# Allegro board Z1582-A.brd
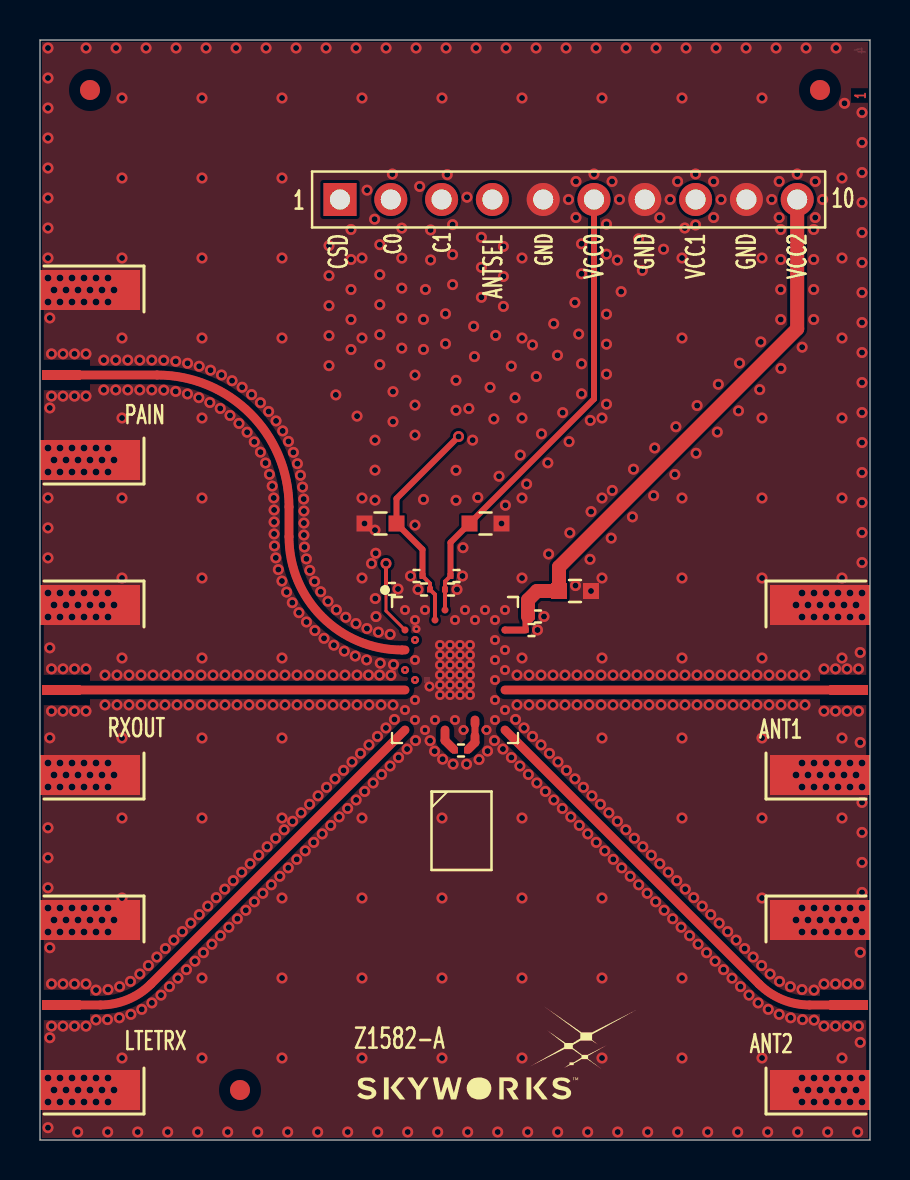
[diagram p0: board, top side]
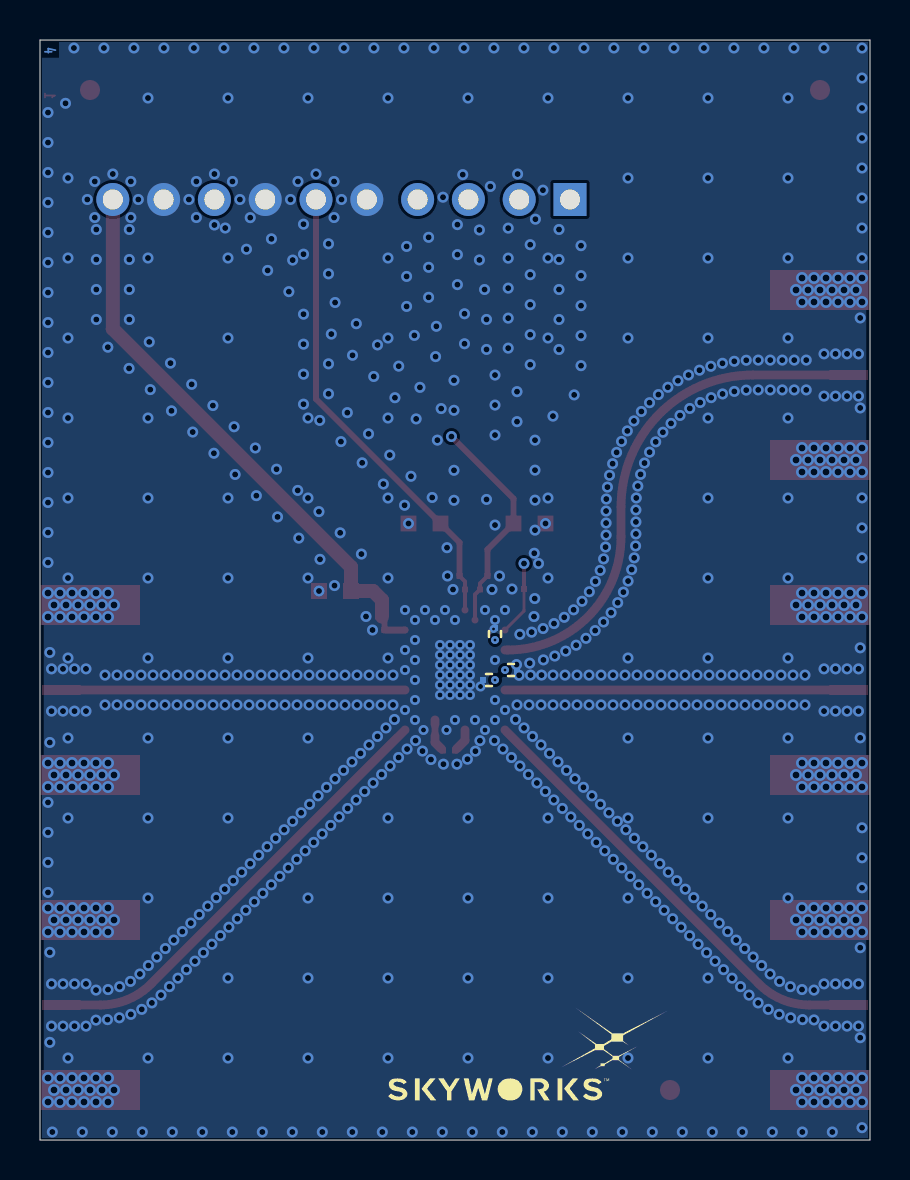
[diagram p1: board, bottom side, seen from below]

Outline 41.5 x 55 mm; copper layers: TOP, L2, L3, BOTTOM. Coordinates in mm from the lower left corner of the outline.
Outline path: 0,55 0,0 41.5,0 41.5,55 0,55

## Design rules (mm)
constraint set DEFAULT: min track width 0.15
net group RF: nets ANT1 ANT2 LTETRX N13114708 N13124264 PAIN RXOUT
nets with their own width: min track width 0.5; nets GND

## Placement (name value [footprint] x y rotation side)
C2  20pF  [SMDC600X300]  24.57 25.5 0 top
C3  20pF  [SMDC600X300]  19.2 27.52 180 top
C4  100pF  [SMDC600X300]  24.9 26.18 0 top
C5  20pF  [SMDC600X300]  20.55 27.52 0 top
C6  100pF  [SMDC600X300]  20.82 28.2 0 top
C7  100pF  [SMDC600X300]  18.82 28.2 180 top
C8  DNI  [SMDC600X300]  17.6 27.55 0 top
C9  DNI  [SMDC600X300]  18.75 25.3 90 bottom
C10  DNI  [SMDC600X300]  17.95 23.5 180 bottom
C11  DNI  [SMDC600X300]  19.05 23 0 bottom
C12  1uF  [SMDC1600X800]  26.75 27.45 0 top
C13  1uF  [SMDC1600X800]  22.27 30.82 0 top
C14  1uF  [SMDC1600X800]  17.02 30.82 180 top
J1  RF_5pin  [SMA_CPWG_442_236]  0 6.75 180 top
J2  RF_5pin  [SMA_CPWG_442_236]  0 38.25 180 top
J3  RF_5pin  [SMA_CPWG_442_236]  41.5 6.75 0 top
J4  RF_5pin  [SMA_CPWG_442_236]  0 22.5 180 top
J5  RF_5pin  [SMA_CPWG_442_236]  41.5 22.5 0 top
J6  HEADER 10  [TSW-110-07-G-S]  15 47.02 0 top
NOREF  -  []  0 0 90 top
NOREF#2  -  [unnamed#2]  39 52.5 0 top
NOREF#3  -  []  0 55 0 top
NOREF#4  -  []  -103.71 -52.7 0 top
NOREF#5  -  [unnamed#2]  10 2.5 0 top
NOREF#6  -  [unnamed#2]  2.5 52.5 0 top
NOREF#7  -  []  -78.31 -116.2 0 top
NOREF#8  -  []  15.43 1.55 0 top
NOREF#9  -  []  86.8 64.75 0 top
NOREF#10  -  []  24.52 1.5 180 bottom
R1  0R  [SMDC600X300]  21.05 19.48 0 top
U1  SKY66425-11  [SP03-D512_01]  20.75 23.5 0 top

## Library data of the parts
C2-C14 = C
J1-J5 = RF_5pin
J6 = HEADER 10
R1 = R
U1 = SKY66425-11

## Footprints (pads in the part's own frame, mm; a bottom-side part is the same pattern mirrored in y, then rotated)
SMA_CPWG_442_236
  rect 1.932x0.5 smd: 1(-1.1,0)
  rect 5x2 smd: 2(-2.5,4.25) 3(-2.5,-4.25) 4(-2.5,4.25) 5(-2.5,-4.25)
SMDC600X300
  rect 0.3x0.3 smd: 1(-0.3,0) 2(0.3,0)
SMDC1600X800
  rect 0.8x0.8 smd: 1(-0.8,0) 2(0.8,0)
SP03-D512_01
  round 0.35 smd: A01(-2.5,3) A03(-2.5,2) A05(-2.5,1) A07(-2.5,0) A09(-2.5,-1) A11(-2.5,-2) A13(-2.5,-3) B02(-2,2.5) B04(-2,1.5) B06(-2,0.5) B08(-2,-0.5) B10(-2,-1.5) B12(-2,-2.5) C01(-1.5,3) C13(-1.5,-3) D02(-1,2.5) D04(-0.75,1.25) D05(-0.75,0.75) D06(-0.75,0.25) D07(-0.75,-0.25) D08(-0.75,-0.75) D09(-0.75,-1.25) D12(-1,-2.5) E01(-0.5,3) E04(-0.25,1.25) E05(-0.25,0.75) E06(-0.25,0.25) E07(-0.25,-0.25) E08(-0.25,-0.75) E09(-0.25,-1.25) E13(-0.5,-3) F02(0,2.5) F12(0,-2.5) G01(0.5,3) G04(0.25,1.25) G05(0.25,0.75) G06(0.25,0.25) G07(0.25,-0.25) G08(0.25,-0.75) G09(0.25,-1.25) G13(0.5,-3) H02(1,2.5) H04(0.75,1.25) H05(0.75,0.75) H06(0.75,0.25) H07(0.75,-0.25) H08(0.75,-0.75) H09(0.75,-1.25) H12(1,-2.5) J01(1.5,3) J13(1.5,-3) K02(2,2.5) K04(2,1.5) K06(2,0.5) K08(2,-0.5) K10(2,-1.5) K12(2,-2.5) L01(2.5,3) L03(2.5,2) L05(2.5,1) L07(2.5,0) L09(2.5,-1) L11(2.5,-2) L13(2.5,-3)
TSW-110-07-G-S
  rect 1.65x1.65 hole 1: 1(0,0)
  round 1.65 hole 1: 2(2.54,0) 3(5.08,0) 4(7.62,0) 5(10.16,0) 6(12.7,0) 7(15.24,0) 8(17.78,0) 9(20.32,0) 10(22.86,0)
unnamed#2
  round 1 smd: (0,0)

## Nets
GND: C2.2 C3.2 C4.2 C5.2 C6.2 C7.2 C8.2 C9.2 C10.2 C11.2 C12.2 C13.2 C14.2 J1.2 J1.3 J1.4 J1.5 J2.2 J2.3 J2.4 J2.5 J3.2 J3.3 J3.4 J3.5 J4.2 J4.3 J4.4 J4.5 J5.2 J5.3 J5.4 J5.5 J6.5 J6.7 J6.9 U1.A01 U1.A11 U1.B02 U1.B06 U1.B10 U1.B12 U1.C01 U1.C13 U1.D04 U1.D05 U1.D06 U1.D07 U1.D08 U1.D09 U1.D12 U1.E04 U1.E05 U1.E06 U1.E07 U1.E08 U1.E09 U1.F02 U1.F12 U1.G01 U1.G04 U1.G05 U1.G06 U1.G07 U1.G08 U1.G09 U1.G13 U1.H02 U1.H04 U1.H05 U1.H06 U1.H07 U1.H08 U1.H09 U1.J01 U1.J13 U1.K02 U1.K04 U1.K06 U1.K08 U1.K10 U1.K12 U1.L01 U1.L05 U1.L07 U1.L11
VCC0: C5.1 C6.1 C13.1 J6.6 U1.E01
VCC1: C3.1 C7.1 C14.1 J6.8 U1.D02
VCC2: C2.1 C4.1 C12.1 J6.10 U1.L03(VCC2)
ANT1: J5.1(SIG) U1.L09
ANT2: J3.1(SIG) U1.L13
ANTSEL: C11.1 J6.4 U1.B08
C0: C9.1 J6.2 U1.B04
C1: C10.1 J6.3 U1.A07
CSD: C8.1 J6.1 U1.A03
LTETRX: J1.1(SIG) U1.A13
PAIN: J2.1(SIG) U1.A05
RXOUT: J4.1(SIG) U1.A09
N13114708: R1.2 U1.H12
N13124264: R1.1 U1.E13

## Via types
v1: diameter 0.4, hole 0.15, TOP to BOTTOM, 4 vias
v2: diameter 0.55, hole 0.3, TOP to BOTTOM, 735 vias
v3: diameter 0.6, hole 0.35, TOP to BOTTOM, 180 vias
v4: diameter 0.5, hole 0.25, TOP to BOTTOM, 51 vias

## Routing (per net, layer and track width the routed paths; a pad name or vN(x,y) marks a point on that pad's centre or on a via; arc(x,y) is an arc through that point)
GND:
  vias: v1(18.82,25.55) v2(0.4,54.6) v2(0.4,53.1) v2(0.4,51.6) v2(0.4,50.1) v2(0.4,48.6) v2(0.4,47.1) v2(0.4,45.6) v2(0.4,44.1) v2(0.4,32.11) v2(0.4,30.61) v2(0.4,29.11) v2(0.4,15.61) v2(0.4,14.11) v2(0.4,12.61) v2(0.4,0.62) v2(0.49,41.1) v2(0.49,36.6) v2(0.49,24.61) v2(0.49,20.11) v2(0.49,9.61) v2(0.49,5.11) v2(0.57,39.31) v2(0.57,37.19) v2(0.57,23.56) v2(0.57,21.44) v2(0.57,7.81) v2(0.57,5.69) v2(1.15,39.31) v2(1.15,37.19) v2(1.15,23.56) v2(1.15,21.44) v2(1.15,7.81) v2(1.15,5.69) v2(1.72,39.31) v2(1.72,37.19) v2(1.72,23.56) v2(1.72,21.44) v2(1.72,7.81) v2(1.72,5.69) v2(1.88,0.4) v2(2.3,39.31) v2(2.3,37.19) v2(2.3,23.56) v2(2.3,21.44) v2(2.3,7.81) v2(2.3,5.69) v2(2.3,54.6) v2(2.8,7.5) v2(2.8,6) v2(3.19,39) v2(3.19,37.5) v2(3.25,23.25) v2(3.25,21.75) v2(3.37,6.02) v2(3.38,0.4) v2(3.4,7.52) v2(3.79,39) v2(3.79,37.5) v2(3.8,54.6) v2(3.85,23.25) v2(3.85,21.75) v2(3.98,7.67) v2(3.97,6.11) v2(4.1,52.1) v2(4.1,48.1) v2(4.1,44.1) v2(4.1,40.1) v2(4.1,36.1) v2(4.1,32.1) v2(4.1,28.1) v2(4.1,24.1) v2(4.1,20.1) v2(4.1,16.1) v2(4.1,12.1) v2(4.1,4.1) v2(4.39,39) v2(4.39,37.5) v2(4.45,23.25) v2(4.45,21.75) v2(4.52,7.93) v2(4.54,6.28) v2(4.88,0.4) v2(4.99,39) v2(4.99,37.5) v2(4.99,8.3) v2(5.05,23.25) v2(5.05,21.75) v2(5.09,6.53) v2(5.3,54.6) v2(5.42,8.72) v2(5.59,39) v2(5.59,37.5) v2(5.59,6.86) v2(5.65,23.25) v2(5.65,21.75) v2(5.84,9.15) v2(6.05,7.24) v2(6.19,38.99) v2(6.19,37.49) v2(6.25,23.25) v2(6.25,21.75) v2(6.27,9.57) v2(6.38,0.4) v2(6.47,7.67) v2(6.69,10) v2(6.79,38.94) v2(6.79,37.43) v2(6.8,54.6) v2(6.85,23.25) v2(6.85,21.75) v2(6.9,8.09) v2(7.12,10.42) v2(7.38,38.84) v2(7.37,37.3) v2(7.32,8.52) v2(7.45,23.25) v2(7.45,21.75) v2(7.54,10.85) v2(7.75,8.94) v2(7.88,0.4) v2(7.96,38.69) v2(7.94,37.12) v2(7.96,11.27) v2(8.1,52.1) v2(8.1,48.1) v2(8.1,44.1) v2(8.1,40.1) v2(8.1,36.1) v2(8.1,32.1) v2(8.1,28.1) v2(8.1,24.1) v2(8.05,23.25) v2(8.05,21.75) v2(8.1,20.1) v2(8.1,16.1) v2(8.1,8.1) v2(8.1,4.1) v2(8.17,9.37) v2(8.3,54.6) v2(8.39,11.69) v2(8.49,36.87) v2(8.53,38.49) v2(8.6,9.79) v2(8.65,23.25) v2(8.65,21.75) v2(8.81,12.12) v2(9.08,38.25) v2(9.01,36.58) v2(9.02,10.21) v2(9.25,23.25) v2(9.25,21.75) v2(9.24,12.54) v2(9.38,0.4) v2(9.5,36.23) v2(9.44,10.64) v2(9.6,37.96) v2(9.66,12.97) v2(9.8,54.6) v2(9.85,23.25) v2(9.85,21.75) v2(9.87,11.06) v2(9.95,35.83) v2(10.09,13.39) v2(10.11,37.64) v2(10.29,11.49) v2(10.36,35.39) v2(10.45,23.25) v2(10.45,21.75) v2(10.58,37.27) v2(10.51,13.82) v2(10.71,34.91) v2(10.72,11.91) v2(10.88,0.4) v2(10.93,14.24) v2(11.02,36.87) v2(11.02,34.39) v2(11.05,23.25) v2(11.05,21.75) v2(11.14,12.34) v2(11.28,33.85) v2(11.3,54.6) v2(11.36,14.66) v2(11.43,36.43) v2(11.47,33.28) v2(11.57,12.76) v2(11.61,32.7) v2(11.69,32.1) v2(11.65,23.25) v2(11.65,21.75) v2(11.7,31.5) v2(11.7,30.9) v2(11.7,30.3) v2(11.72,29.7) v2(11.79,29.11) v2(11.78,15.09) v2(11.8,35.95) v2(11.92,28.52) v2(11.99,13.18) v2(12.1,52.1) v2(12.1,48.1) v2(12.1,44.1) v2(12.1,40.1) v2(12.1,27.95) v2(12.1,24.1) v2(12.1,20.1) v2(12.1,16.1) v2(12.1,12.1) v2(12.1,8.1) v2(12.1,4.1) v2(12.13,35.45) v2(12.25,23.25) v2(12.25,21.75) v2(12.21,15.51) v2(12.33,27.4) v2(12.38,0.4) v2(12.42,34.93) v2(12.41,13.61) v2(12.67,34.38) v2(12.61,26.87) v2(12.63,15.94) v2(12.8,54.6) v2(12.87,33.82) v2(12.85,23.25) v2(12.85,21.75) v2(12.84,14.03) v2(12.95,26.37) v2(13.02,33.24) v2(13.06,16.36) v2(13.13,32.64) v2(13.19,32.05) v2(13.2,31.45) v2(13.2,30.85) v2(13.2,30.25) v2(13.22,29.65) v2(13.26,14.46) v2(13.32,29.06) v2(13.32,25.9) v2(13.49,28.48) v2(13.45,23.25) v2(13.45,21.75) v2(13.48,16.79) v2(13.69,14.88) v2(13.73,27.93) v2(13.74,25.47) v2(13.88,0.4) v2(13.9,17.21) v2(14.03,27.41) v2(14.05,23.25) v2(14.05,21.75) v2(14.11,15.31) v2(14.2,25.08) v2(14.3,54.6) v2(14.4,26.94) v2(14.33,17.63) v2(14.45,44.72) v2(14.45,43.22) v2(14.45,41.72) v2(14.45,40.22) v2(14.45,38.72) v2(14.54,15.73) v2(14.69,24.74) v2(14.65,23.25) v2(14.65,21.75) v2(14.79,37.26) v2(14.75,18.06) v2(14.82,26.51) v2(14.96,16.15) v2(15.18,18.48) v2(15.29,26.14) v2(15.21,24.44) v2(15.25,23.25) v2(15.25,21.75) v2(15.38,16.58) v2(15.38,0.4) v2(15.55,45.52) v2(15.55,44.02) v2(15.55,42.52) v2(15.55,41.02) v2(15.55,39.52) v2(15.6,18.91) v2(15.76,24.2) v2(15.8,54.6) v2(15.85,36.19) v2(15.8,25.82) v2(15.85,23.25) v2(15.85,21.75) v2(15.81,17) v2(16.1,52.1) v2(16.1,44.1) v2(16.1,40.1) v2(16.1,32.1) v2(16.1,28.1) v2(16.03,19.33) v2(16.1,16.1) v2(16.1,12.1) v2(16.1,8.1) v2(16.1,4.1) v2(16.23,30.82) v2(16.23,17.43) v2(16.35,47.49) v2(16.35,25.57) v2(16.33,24.01) v2(16.43,23.25) v2(16.45,21.75) v2(16.45,19.75) v2(16.57,28.82) v2(16.66,17.85) v2(16.73,46.04) v2(16.75,34.99) v2(16.75,33.49) v2(16.75,31.99) v2(16.75,30.49) v2(16.79,29.34) v2(16.76,27.07) v2(16.8,26.17) v2(16.87,20.18) v2(16.88,0.4) v2(16.99,44.77) v2(16.99,43.27) v2(16.99,41.77) v2(16.99,40.27) v2(16.99,38.77) v2(16.92,25.39) v2(16.98,23.25) v2(17.01,23.84) v2(17.05,21.75) v2(17.08,18.28) v2(17.3,20.6) v2(17.3,54.6) v2(17.51,25.28) v2(17.55,23.24) v2(17.5,18.7) v2(17.62,48.3) v2(17.65,37.42) v2(17.65,35.92) v2(17.68,23.77) v2(17.65,21.75) v2(17.72,21.03) v2(17.9,27.55) v2(17.93,19.12) v2(18.09,45.59) v2(18.09,44.09) v2(18.09,42.59) v2(18.09,41.09) v2(18.09,39.59) v2(18.35,19.55) v2(18.38,0.4) v2(18.52,28.2) v2(18.75,38.25) v2(18.75,36.75) v2(18.75,35.25) v2(18.75,30.75) v2(18.78,19.97) v2(18.8,54.6) v2(18.9,27.52) v2(18.98,47.68) v2(19.18,41.03) v2(19.18,39.53) v2(19.18,32.03) v2(19.27,42.52) v2(19.53,45.5) v2(19.53,44) v2(19.5,19.97) v2(19.73,19.44) v2(19.88,0.4) v2(20.1,52.1) v2(20.1,16.1) v2(20.1,12.1) v2(20.1,8.1) v2(20.1,4.1) v2(20.13,19.04) v2(20.27,41.31) v2(20.27,39.81) v2(20.3,54.6) v2(20.36,48.27) v2(20.63,45.77) v2(20.63,44.27) v2(20.63,42.77) v2(20.65,18.79) v2(20.8,37.99) v2(20.8,36.49) v2(20.8,33.49) v2(20.8,31.99) v2(20.85,27.52) v2(21.15,29.62) v2(21.12,28.2) v2(21.35,47.14) v2(21.33,18.79) v2(21.38,0.4) v2(21.44,36.57) v2(21.68,40.69) v2(21.63,34.99) v2(21.72,39.17) v2(21.8,54.6) v2(21.89,32.13) v2(21.95,19.02) v2(22.07,45.13) v2(22.07,43.63) v2(22.07,42.13) v2(22.38,19.45) v2(22.5,37.63) v2(22.69,36.05) v2(22.78,40.23) v2(22.72,19.97) v2(22.88,0.4) v2(22.95,33.19) v2(23.07,30.82) v2(23.17,44.68) v2(23.17,43.18) v2(23.17,41.68) v2(23.15,19.55) v2(23.27,31.74) v2(23.3,54.6) v2(23.56,38.69) v2(23.57,19.12) v2(23.75,37.11) v2(23.78,21.03) v2(23.85,23.25) v2(23.85,21.75) v2(24,18.7) v2(24.01,34.25) v2(24.1,52.1) v2(24.1,44.1) v2(24.1,40.1) v2(24.1,36.1) v2(24.1,32.1) v2(24.1,28.1) v2(24.1,24.1) v2(24.1,16.1) v2(24.1,12.1) v2(24.1,8.1) v2(24.1,4.1) v2(24.2,20.6) v2(24.33,32.8) v2(24.38,0.4) v2(24.45,23.25) v2(24.45,21.75) v2(24.42,18.28) v2(24.62,39.75) v2(24.63,20.18) v2(24.8,54.6) v2(24.81,38.18) v2(24.88,25.5) v2(24.84,17.85) v2(25.07,35.31) v2(25.05,23.25) v2(25.05,21.75) v2(25.05,19.75) v2(25.2,26.18) v2(25.27,17.43) v2(25.39,33.86) v2(25.43,29.3) v2(25.47,19.33) v2(25.69,40.81) v2(25.65,23.25) v2(25.65,21.75) v2(25.69,17) v2(25.87,39.24) v2(25.9,18.91) v2(25.88,0.4) v2(26.13,36.37) v2(26.12,16.58) v2(26.25,23.25) v2(26.25,21.75) v2(26.3,54.6) v2(26.32,18.48) v2(26.42,47.02) v2(26.45,34.92) v2(26.49,30.36) v2(26.54,16.15) v2(26.8,47.93) v2(26.8,46.12) v2(26.75,41.87) v2(26.77,27.72) v2(26.75,18.06) v2(26.85,23.25) v2(26.85,21.75) v2(26.94,40.3) v2(26.96,15.73) v2(27.07,44.81) v2(27.07,43.31) v2(27.07,38.81) v2(27.07,37.31) v2(27.17,17.63) v2(27.39,15.31) v2(27.38,0.4) v2(27.45,23.25) v2(27.45,21.75) v2(27.51,35.98) v2(27.55,31.42) v2(27.5,29.03) v2(27.55,27.45) v2(27.6,17.21) v2(27.7,48.3) v2(27.8,54.6) v2(27.81,14.88) v2(28.1,52.1) v2(28.1,36.1) v2(28.1,32.1) v2(28.1,28.1) v2(28.1,24.1) v2(28.05,23.25) v2(28.05,21.75) v2(28.1,20.1) v2(28.02,16.79) v2(28.1,12.1) v2(28.1,8.1) v2(28.1,4.1) v2(28.24,14.46) v2(28.32,45.79) v2(28.32,44.29) v2(28.32,41.29) v2(28.32,39.79) v2(28.32,38.29) v2(28.32,36.79) v2(28.44,16.36) v2(28.56,30.09) v2(28.6,47.93) v2(28.61,32.48) v2(28.65,23.25) v2(28.65,21.75) v2(28.66,14.03) v2(28.87,44) v2(28.87,15.94) v2(28.88,0.4) v2(28.98,47.02) v2(29.06,42.42) v2(29.09,13.61) v2(29.25,23.25) v2(29.25,21.75) v2(29.29,15.51) v2(29.3,54.6) v2(29.51,13.18) v2(29.67,33.54) v2(29.62,31.16) v2(29.72,15.09) v2(29.85,23.25) v2(29.85,21.75) v2(29.93,45.06) v2(29.93,12.76) v2(30.12,43.48) v2(30.14,14.66) v2(30.36,12.34) v2(30.38,0.4) v2(30.45,23.25) v2(30.45,21.75) v2(30.57,14.24) v2(30.68,32.22) v2(30.73,34.6) v2(30.78,11.91) v2(30.8,54.6) v2(30.99,46.12) v2(30.99,13.82) v2(31.05,23.25) v2(31.05,21.75) v2(31.18,44.54) v2(31.21,11.49) v2(31.41,13.39) v2(31.5,47.02) v2(31.65,23.25) v2(31.65,21.75) v2(31.63,11.06) v2(31.8,35.66) v2(31.74,33.28) v2(31.88,47.93) v2(31.84,12.97) v2(31.88,0.4) v2(32.1,52.1) v2(32.1,44.1) v2(32.1,40.1) v2(32.1,32.1) v2(32.1,28.1) v2(32.1,24.1) v2(32.1,20.1) v2(32.1,16.1) v2(32.06,10.64) v2(32.1,8.1) v2(32.1,4.1) v2(32.24,45.6) v2(32.25,23.25) v2(32.25,21.75) v2(32.26,12.54) v2(32.3,54.6) v2(32.48,10.21) v2(32.69,12.12) v2(32.78,48.3) v2(32.78,45.75) v2(32.86,36.72) v2(32.8,34.34) v2(32.85,23.25) v2(32.85,21.75) v2(32.9,9.79) v2(33.11,11.69) v2(33.33,9.37) v2(33.38,0.4) v2(33.45,23.25) v2(33.45,21.75) v2(33.54,11.27) v2(33.68,47.93) v2(33.68,46.12) v2(33.75,8.94) v2(33.8,54.6) v2(33.86,35.4) v2(33.92,37.78) v2(33.96,10.85) v2(34.06,47.02) v2(34.05,23.25) v2(34.05,21.75) v2(34.18,8.52) v2(34.38,10.42) v2(34.65,23.25) v2(34.65,21.75) v2(34.6,8.09) v2(34.81,10) v2(34.88,0.4) v2(34.98,38.84) v2(34.93,36.46) v2(35.03,7.67) v2(35.25,23.25) v2(35.25,21.75) v2(35.23,9.57) v2(35.3,54.6) v2(35.45,7.24) v2(35.66,9.15) v2(35.85,23.25) v2(35.85,21.75) v2(35.99,37.52) v2(35.91,6.86) v2(36.1,52.1) v2(36.1,44.1) v2(36.04,39.9) v2(36.1,36.1) v2(36.1,32.1) v2(36.1,28.1) v2(36.1,24.1) v2(36.1,20.1) v2(36.1,16.1) v2(36.1,12.1) v2(36.08,8.72) v2(36.1,4.1) v2(36.38,0.4) v2(36.45,23.25) v2(36.45,21.75) v2(36.41,6.53) v2(36.58,47.02) v2(36.51,8.3) v2(36.8,54.6) v2(36.96,47.93) v2(36.96,46.12) v2(36.98,7.93) v2(36.96,6.28) v2(37.03,45.52) v2(37.03,44.02) v2(37.03,42.52) v2(37.03,41.02) v2(37.05,38.58) v2(37.05,23.25) v2(37.05,21.75) v2(37.52,7.67) v2(37.53,6.11) v2(37.65,23.25) v2(37.65,21.75) v2(37.86,48.3) v2(37.88,0.4) v2(38.1,7.52) v2(38.11,39.64) v2(38.13,6.02) v2(38.25,23.25) v2(38.25,21.75) v2(38.3,54.6) v2(38.69,45.52) v2(38.69,44.02) v2(38.69,42.52) v2(38.69,41.02) v2(38.7,7.5) v2(38.76,47.93) v2(38.76,46.12) v2(38.7,5.99) v2(39.14,47.02) v2(39.2,23.56) v2(39.2,21.44) v2(39.2,7.81) v2(39.2,5.69) v2(39.38,0.4) v2(39.78,23.56) v2(39.78,21.44) v2(39.78,7.81) v2(39.78,5.69) v2(39.8,54.6) v2(40.1,48.1) v2(40.1,44.1) v2(40.1,40.1) v2(40.1,36.1) v2(40.1,32.1) v2(40.1,28.1) v2(40.1,24.1) v2(40.1,20.1) v2(40.1,16.1) v2(40.1,4.1) v2(40.22,51.83) v2(40.35,23.56) v2(40.35,21.44) v2(40.35,7.81) v2(40.35,5.69) v2(40.88,0.4) v2(40.93,23.56) v2(40.93,21.44) v2(40.93,7.81) v2(40.93,5.69) v2(41.01,24.38) v2(41.01,19.88) v2(41.01,9.38) v2(41.01,4.88) v2(41.1,51.37) v2(41.1,49.87) v2(41.1,48.37) v2(41.1,46.87) v2(41.1,45.37) v2(41.1,43.87) v2(41.1,42.37) v2(41.1,40.87) v2(41.1,39.37) v2(41.1,37.87) v2(41.1,36.37) v2(41.1,34.87) v2(41.1,33.37) v2(41.1,31.87) v2(41.1,30.37) v2(41.1,28.87) v2(41.1,16.88) v2(41.1,15.38) v2(41.1,13.88) v2(41.1,12.38) v3(0.4,43.1) v3(0.4,41.9) v3(0.4,34.6) v3(0.4,33.4) v3(0.4,27.35) v3(0.4,26.15) v3(0.4,18.85) v3(0.4,17.65) v3(0.4,11.6) v3(0.4,10.4) v3(0.4,3.1) v3(0.4,1.9) v3(0.7,42.5) v3(0.7,34) v3(0.7,26.75) v3(0.7,18.25) v3(0.7,11) v3(0.7,2.5) v3(1,43.1) v3(1,41.9) v3(1,34.6) v3(1,33.4) v3(1,27.35) v3(1,26.15) v3(1,18.85) v3(1,17.65) v3(1,11.6) v3(1,10.4) v3(1,3.1) v3(1,1.9) v3(1.3,42.5) v3(1.3,34) v3(1.3,26.75) v3(1.3,18.25) v3(1.3,11) v3(1.3,2.5) v3(1.6,43.1) v3(1.6,41.9) v3(1.6,34.6) v3(1.6,33.4) v3(1.6,27.35) v3(1.6,26.15) v3(1.6,18.85) v3(1.6,17.65) v3(1.6,11.6) v3(1.6,10.4) v3(1.6,3.1) v3(1.6,1.9) v3(1.9,42.5) v3(1.9,34) v3(1.9,26.75) v3(1.9,18.25) v3(1.9,11) v3(1.9,2.5) v3(2.2,43.1) v3(2.2,41.9) v3(2.2,34.6) v3(2.2,33.4) v3(2.2,27.35) v3(2.2,26.15) v3(2.2,18.85) v3(2.2,17.65) v3(2.2,11.6) v3(2.2,10.4) v3(2.2,3.1) v3(2.2,1.9) v3(2.5,42.5) v3(2.5,34) v3(2.5,26.75) v3(2.5,18.25) v3(2.5,11) v3(2.5,2.5) v3(2.8,43.1) v3(2.8,41.9) v3(2.8,34.6) v3(2.8,33.4) v3(2.8,27.35) v3(2.8,26.15) v3(2.8,18.85) v3(2.8,17.65) v3(2.8,11.6) v3(2.8,10.4) v3(2.8,3.1) v3(2.8,1.9) v3(3.1,42.5) v3(3.1,34) v3(3.1,26.75) v3(3.1,18.25) v3(3.1,11) v3(3.1,2.5) v3(3.4,43.1) v3(3.4,41.9) v3(3.4,34.6) v3(3.4,33.4) v3(3.4,27.35) v3(3.4,26.15) v3(3.4,18.85) v3(3.4,17.65) v3(3.4,11.6) v3(3.4,10.4) v3(3.4,3.1) v3(3.4,1.9) v3(3.7,42.5) v3(3.7,34) v3(3.7,26.75) v3(3.7,18.25) v3(3.7,11) v3(3.7,2.5) v3(37.8,26.75) v3(37.8,18.25) v3(37.8,11) v3(37.8,2.5) v3(38.1,27.35) v3(38.1,26.15) v3(38.1,18.85) v3(38.1,17.65) v3(38.1,11.6) v3(38.1,10.4) v3(38.1,3.1) v3(38.1,1.9) v3(38.4,26.75) v3(38.4,18.25) v3(38.4,11) v3(38.4,2.5) v3(38.7,27.35) v3(38.7,26.15) v3(38.7,18.85) v3(38.7,17.65) v3(38.7,11.6) v3(38.7,10.4) v3(38.7,3.1) v3(38.7,1.9) v3(39,26.75) v3(39,18.25) v3(39,11) v3(39,2.5) v3(39.3,27.35) v3(39.3,26.15) v3(39.3,18.85) v3(39.3,17.65) v3(39.3,11.6) v3(39.3,10.4) v3(39.3,3.1) v3(39.3,1.9) v3(39.6,26.75) v3(39.6,18.25) v3(39.6,11) v3(39.6,2.5) v3(39.9,27.35) v3(39.9,26.15) v3(39.9,18.85) v3(39.9,17.65) v3(39.9,11.6) v3(39.9,10.4) v3(39.9,3.1) v3(39.9,1.9) v3(40.2,26.75) v3(40.2,18.25) v3(40.2,11) v3(40.2,2.5) v3(40.5,27.35) v3(40.5,26.15) v3(40.5,18.85) v3(40.5,17.65) v3(40.5,11.6) v3(40.5,10.4) v3(40.5,3.1) v3(40.5,1.9) v3(40.8,26.75) v3(40.8,18.25) v3(40.8,11) v3(40.8,2.5) v3(41.1,27.35) v3(41.1,26.15) v3(41.1,18.85) v3(41.1,17.65) v3(41.1,11.6) v3(41.1,10.4) v3(41.1,3.1) v3(41.1,1.9) v4(18.25,26.5) v4(18.25,21.5) v4(18.75,26) v4(18.75,24) v4(18.75,22) v4(18.75,21) v4(19.25,26.5) v4(19.25,20.5) v4(19.48,22.68) v4(19.75,21) v4(20,24.75) v4(20,24.25) v4(20,23.75) v4(20,23.25) v4(20,22.75) v4(20,22.25) v4(20.5,24.75) v4(20.5,24.25) v4(20.5,23.75) v4(20.5,23.25) v4(20.5,22.75) v4(20.5,22.25) v4(20.75,26) v4(20.75,21) v4(21,24.75) v4(21,24.25) v4(21,23.75) v4(21,23.25) v4(21,22.75) v4(21,22.25) v4(21.18,20.5) v4(21.25,26.5) v4(21.5,24.75) v4(21.5,24.25) v4(21.5,23.75) v4(21.5,23.25) v4(21.5,22.75) v4(21.5,22.25) v4(21.75,26) v4(22.25,26.5) v4(22.32,20.5) v4(22.75,26) v4(22.75,25) v4(22.75,24) v4(22.75,23) v4(22.75,22) v4(22.75,21) v4(23.25,26.5) v4(23.25,24.5) v4(23.25,23.5) v4(23.25,21.5)
VCC0: length 23.6
  TOP w0.2: C6.1 20.25,27.93 C5.1 U1.E01
  TOP w0.3: C6.1 20.52,29.88 C13.1 27.7,37.05 J6.6
VCC1: length 28
  TOP w0.2: C7.1 19.5,27.82 C3.1 19.75,27.27 U1.D02
  TOP w0.3: C7.1 19.12,29.52 C14.1 17.82,32.07 v2(20.93,35.17)
  L3 w0.3: v2(20.93,35.17) J6.8
VCC2: length 29.1
  TOP w0.3: 24.27,25.5 24.27,26.18 C4.1
  TOP w0.35: U1.L03 24.27,25.5
  TOP w0.7: J6.10 37.86,40.56 25.95,28.65 C12.1 24.85,27.45 24.4,27 24.4,26.18
ANT1: length 17.1
  TOP w0.442: U1.L09 J5.1
ANT2: length 22.7
  TOP w0.442: J3.1 38.49,6.75 arc(37.11,7.02) 35.95,7.8 U1.L13
ANTSEL: length 25.8
  L3 w0.15: J6.4 22.62,40.84 20.25,38.48 20.25,25.9 19.52,25.18 19.52,23.4 19.12,23 v1(18.75,23)
C0: length 23.3
  L3 w0.15: J6.2 17.54,38.94 18.2,38.27 18.2,28.93 17.31,28.04 17.31,26.44 v1(18.75,25)
C1: length 24.8
  L3 w0.15: v1(18.25,23.5) 19.1,23.5 19.23,23.62 19.23,25.3 19.73,25.8 19.73,42.2 20.08,42.55 J6.3
CSD: length 22.9
  TOP w0.15: C8.1 17.3,26.45 U1.A03
  TOP w0.2: C8.1 v2(17.3,28.82)
  L3 w0.15: v2(17.3,28.82) 17.3,35.52 15,37.83 J6.1
LTETRX: length 22.7
  TOP w0.442: U1.A13 5.55,7.8 arc(4.39,7.02) 3.01,6.75 J1.1
PAIN: length 25.6
  TOP w0.442: U1.A05 18.11,24.5 arc(14.11,26.16) 12.45,30.16 12.45,31.65 arc(10.52,36.32) 5.85,38.25 J2.1
RXOUT: length 17.1
  TOP w0.442: U1.A09 J4.1
N13114708: length 1.7
  TOP w0.3: R1.2 21.43,19.55
  TOP w0.35: 21.75,20.2 21.75,20.8
  TOP w0.442: 21.43,19.55 21.75,19.88 21.75,20.2 ; 21.75,20.8 U1.H12
N13124264: length 1.2
  TOP w0.3: R1.1 20.68,19.55
  TOP w0.442: 20.68,19.55 20.25,19.98 U1.E13

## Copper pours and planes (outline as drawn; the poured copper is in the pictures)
GND on TOP, BOTTOM, L2, L3: 41.4,54.9 41.4,0.1 0.1,0.1 0.1,54.9

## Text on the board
BOTTOM: 4
User.Comments: 50 OHM +/-10% | CPW=0.442mm | GAP=0.236mm | REFGND | OVERALL BOARD THICKNESS (METAL-TO-METAL) : 1.5 mm +/- 10%
TOP: 1
Ref Des/Silkscreen Top: C0 | C1 | GND | PAIN | RXOUT | LTETRX | ANT2 | ANT1 | CSD | ANTSEL | VCC0 | VCC1 | VCC2 | Z1582-A
L2: 2
L3: 3
User.12: NOTES:  UNLESS OTHERWISE SPECIFIED | 1.  ALL DATA IS VIEWED FROM TOP SURFACE. | 2.  FABRICATE IN ACCORDANCE WITH IPC-6012, CLASS 2, ACCEPT PER IPC-A-600 CLASS 2 | 3.  MATERIAL: SEE DETAIL 'A' FOR MATERIAL, THICKNESS AND BEGINNING FOIL WEIGHTS. | 4.  COPPER PLATE MINIMUM 0.025mm THICKNESS IN THRU HOLE VIAS. | 5.  FINISH: ENIG PER IPC-4552 | 6.  APPLY GREEN LIQUID PHOTOIMAGABLE SOLDERMASK OVER BARE COPPER (SMOBC) TO THE TOP | AND BOTTOM SURFACES OF THE PRINTED WIRING BOARD. | 7.  APPLY DESIGNATIONS TO TOP AND BOTTOM SURFACES USING PERMANENT SOLVENT INK AS DEFINED | BY THE ARTWORK. COLOR SHALL BE WHITE. | 8.  CONDUCTORS SPECIFIED IN DETAIL 'A' ARE CONTROLLED IMPEDANCE LINES. SHALL BE TESTED FOR | FOR THE SPECIFIED IMPEDANCE(S). | 8A. CONDUCTORS AND GAP TOLERANCE SHALL BE +/- 0.025MM. | 9.  MINIMUM CONDUCTOR WIDTH IS 0.1MM. | 10. MINIMUM CONDUCTOR TO CONDUCTOR SPACING IS 0.1MM. | 11. FINISHED BOARD THICKNESS SHALL BE PER DETAIL 'A'. | 12. LAYER TO LAYER REGISTRATION TO BE +/- 0.075MM. | 13. ALL HOLES SHALL BE LOCATED WITHIN HOLE TO PAD TANGENCY. | 14. SUPPLIER ID/PART NUMBER AND LOT NUMBER ARE REQUIRED TO BE LOCATED ON BOTTOM SURFACE. | 15. ALL VIA DRILL HOLES SHALL BE FILLED WITH NON-CONDUCTIVE MATERIAL AND PLATED OVER | WITH A MINIMUM OF 0.015MM OF CU. | 16. PLATED DRILLS =< 400um MAY HAVE TOLERANCE +80um/-NOMINAL
User.32: SYMBOL | SIZE | 150.0 | 250.0 | 300.0 | 350.0 | 1000.0 | PLATED | DRILL CHART: TOP to BOTTOM | ALL UNITS ARE IN MICRONS | QTY | 4 | 51 | 735 | 180 | 10 | TOLERANCE | +80.0/-150.0 | +80.0/-80.0 | SEE NOTE
